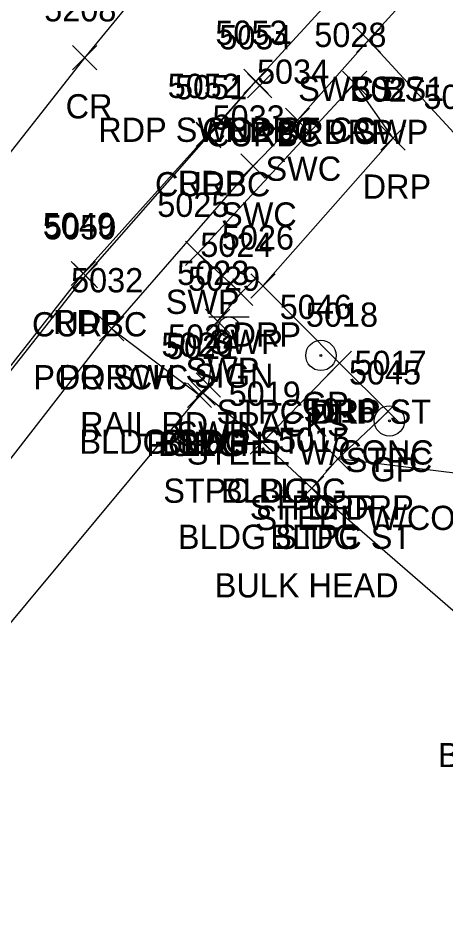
# Model space of a CAD drawing. Extents: x 1618146 to 1620418, y 640749 to 641927.
# Drawn here: x 1620267.4 to 1620302.7, y 640856.8 to 640931.1 of the extents above; entities that cross this region are included whole.
import ezdxf

# ---------------------------------------------------------------- set-up
doc = ezdxf.new("R2010")
doc.units = 0
for name, color, linetype in [('L_A', 7, 'Continuous'), ('L_C', 7, 'Continuous'), ('L_I', 7, 'Continuous'), ('L_TIC', 7, 'Continuous'), ('LBC', 7, 'Continuous'), ('LBF', 7, 'Continuous'), ('LELB', 7, 'Continuous'), ('P_A', 7, 'Continuous'), ('P_I', 7, 'Continuous'), ('P_TIC', 7, 'Continuous'), ('PET', 7, 'Continuous'), ('PRC', 7, 'Continuous'), ('R_A', 7, 'Continuous'), ('R_C', 7, 'Continuous'), ('R_I', 7, 'Continuous'), ('R_TIC', 7, 'Continuous'), ('RC', 7, 'Continuous'), ('RDP', 7, 'Continuous'), ('RGP', 7, 'Continuous'), ('RSW', 7, 'Continuous'), ('S_A', 7, 'Continuous'), ('S_C', 7, 'Continuous'), ('S_I', 7, 'Continuous'), ('SSGN', 7, 'Continuous')]:
    doc.layers.add(name, color=color, linetype=linetype)

msp = doc.modelspace()

# ---------------------------------------------------------------- linework, layer by layer
at = {"layer": 'L_TIC'}
for points in [[(1620295.264, 640928.294), (1620297.264, 640930.294)], [(1620297.264, 640928.294), (1620295.264, 640930.294)], [(1620274.079, 640904.51), (1620276.079, 640906.51)], [(1620276.079, 640904.51), (1620274.079, 640906.51)], [(1620292.873, 640901.672), (1620294.873, 640903.672)], [(1620294.873, 640901.672), (1620292.873, 640903.672)], [(1620281.333, 640899.011), (1620283.333, 640901.011)], [(1620283.333, 640899.011), (1620281.333, 640901.011)], [(1620281.333, 640899.011), (1620283.333, 640901.011)], [(1620283.333, 640899.011), (1620281.333, 640901.011)], [(1620281.611, 640899.197), (1620283.611, 640901.197)], [(1620283.611, 640899.197), (1620281.611, 640901.197)], [(1620296.876, 640897.692), (1620298.876, 640899.692)], [(1620298.876, 640897.692), (1620296.876, 640899.692)], [(1620286.512, 640895.159), (1620288.512, 640897.159)], [(1620288.512, 640895.159), (1620286.512, 640897.159)], [(1620286.512, 640895.159), (1620288.512, 640897.159)], [(1620288.512, 640895.159), (1620286.512, 640897.159)], [(1620292.744, 640893.779), (1620294.744, 640895.779)], [(1620294.744, 640893.779), (1620292.744, 640895.779)], [(1620290.579, 640891.357), (1620292.579, 640893.357)], [(1620292.579, 640891.357), (1620290.579, 640893.357)], [(1620290.579, 640891.357), (1620292.579, 640893.357)], [(1620292.579, 640891.357), (1620290.579, 640893.357)]]:
    msp.add_lwpolyline(points, dxfattribs=at)
at = {"layer": 'LBC'}
msp.add_lwpolyline([(1620332.284, 640856.845), (1620331.644, 640857.534), (1620331.352, 640857.923), (1620308.647, 640877.482), (1620307.781, 640878.325), (1620291.579, 640892.357), (1620287.512, 640896.159), (1620282.611, 640900.197), (1620282.333, 640900.011), (1620250.859, 640862.217)], dxfattribs=at)
at = {"layer": 'LBF'}
for points in [[(1620282.333, 640900.011), (1620275.079, 640905.51)], [(1620291.579, 640892.357), (1620293.744, 640894.779), (1620297.876, 640898.692), (1620293.873, 640902.672), (1620287.512, 640896.159)]]:
    msp.add_lwpolyline(points, dxfattribs=at)
at = {"layer": 'LELB'}
msp.add_lwpolyline([(1620336.269, 640857.028), (1620321.811, 640891.079), (1620314, 640906.57), (1620304.27, 640920.632), (1620296.264, 640929.294)], dxfattribs=at)
at = {"layer": 'P_TIC'}
for points in [[(1620271.862, 640926.85), (1620273.862, 640928.85)], [(1620273.862, 640926.85), (1620271.862, 640928.85)], [(1620285.98, 640924.917), (1620287.98, 640926.917)], [(1620287.98, 640924.917), (1620285.98, 640926.917)], [(1620282.046, 640920.534), (1620284.046, 640922.534)], [(1620284.046, 640920.534), (1620282.046, 640922.534)], [(1620271.752, 640909.066), (1620273.752, 640911.066)], [(1620273.752, 640909.066), (1620271.752, 640911.066)]]:
    msp.add_lwpolyline(points, dxfattribs=at)
at = {"layer": 'PET'}
msp.add_lwpolyline([(1620242.431, 640871.412), (1620272.752, 640910.066), (1620283.046, 640921.534), (1620286.98, 640925.917)], dxfattribs=at)
at = {"layer": 'PRC'}
msp.add_lwpolyline([(1620386.404, 641071.706), (1620361.021, 641035.235), (1620336.241, 641002.906), (1620316.225, 640977.168), (1620300.323, 640960.311), (1620296.609, 640956.784), (1620272.862, 640927.85), (1620252.181, 640901.579), (1620233.904, 640877.595)], dxfattribs=at)
at = {"layer": 'R_TIC'}
for points in [[(1620295.264, 640928.294), (1620297.264, 640930.294)], [(1620297.264, 640928.294), (1620295.264, 640930.294)], [(1620285.98, 640924.917), (1620287.98, 640926.917)], [(1620287.98, 640924.917), (1620285.98, 640926.917)], [(1620285.98, 640924.917), (1620287.98, 640926.917)], [(1620287.98, 640924.917), (1620285.98, 640926.917)], [(1620286.299, 640924.544), (1620288.299, 640926.544)], [(1620288.299, 640924.544), (1620286.299, 640926.544)], [(1620294.133, 640924.738), (1620296.133, 640926.738)], [(1620296.133, 640924.738), (1620294.133, 640926.738)], [(1620294.133, 640924.738), (1620296.133, 640926.738)], [(1620296.133, 640924.738), (1620294.133, 640926.738)], [(1620289.412, 640921.708), (1620291.412, 640923.708)], [(1620291.412, 640921.708), (1620289.412, 640923.708)], [(1620282.078, 640920.427), (1620284.078, 640922.427)], [(1620284.078, 640920.427), (1620282.078, 640922.427)], [(1620297.295, 640920.228), (1620299.295, 640922.228)], [(1620299.295, 640920.228), (1620297.295, 640922.228)], [(1620285.747, 640917.928), (1620287.747, 640919.928)], [(1620287.747, 640917.928), (1620285.747, 640919.928)], [(1620281.187, 640910.732), (1620283.187, 640912.732)], [(1620283.187, 640910.732), (1620281.187, 640912.732)], [(1620271.934, 640908.877), (1620273.934, 640910.877)], [(1620273.934, 640908.877), (1620271.934, 640910.877)], [(1620286.564, 640908.036), (1620288.564, 640910.036)], [(1620288.564, 640908.036), (1620286.564, 640910.036)], [(1620284.734, 640907.432), (1620286.734, 640909.432)], [(1620286.734, 640907.432), (1620284.734, 640909.432)], [(1620282.82, 640905.117), (1620284.82, 640907.117)], [(1620284.82, 640905.117), (1620282.82, 640907.117)], [(1620274.079, 640904.51), (1620276.079, 640906.51)], [(1620276.079, 640904.51), (1620274.079, 640906.51)], [(1620292.873, 640901.672), (1620294.873, 640903.672)], [(1620294.873, 640901.672), (1620292.873, 640903.672)], [(1620282.065, 640899.867), (1620284.065, 640901.867)], [(1620284.065, 640899.867), (1620282.065, 640901.867)], [(1620281.611, 640899.197), (1620283.611, 640901.197)], [(1620283.611, 640899.197), (1620281.611, 640901.197)], [(1620292.744, 640893.779), (1620294.744, 640895.779)], [(1620294.744, 640893.779), (1620292.744, 640895.779)]]:
    msp.add_lwpolyline(points, dxfattribs=at)
at = {"layer": 'RC'}
msp.add_lwpolyline([(1620242.61, 640871.403), (1620272.934, 640909.877), (1620283.078, 640921.427), (1620286.98, 640925.917), (1620287.299, 640925.544)], dxfattribs=at)
at = {"layer": 'RDP'}
for points in [[(1620293.873, 640902.672), (1620287.564, 640909.036), (1620298.295, 640921.228), (1620295.133, 640925.738)], [(1620332.284, 640856.845), (1620331.853, 640857.601), (1620331.536, 640858.064), (1620319.856, 640889.812), (1620319.237, 640890.142), (1620321.542, 640891.388), (1620293.744, 640894.779)]]:
    msp.add_lwpolyline(points, dxfattribs=at)
at = {"layer": 'RGP'}
for p, q in [((1620292.337, 640903.311), (1620292.337, 640903.311)), ((1620297.989, 640897.915), (1620297.989, 640897.915))]:
    msp.add_line(p, q, dxfattribs=at)
for centre, radius in [((1620292.337, 640903.311), 1.25), ((1620292.337, 640903.311), 0.0833), ((1620297.989, 640897.915), 1.25), ((1620297.989, 640897.915), 0.0833)]:
    msp.add_circle(centre, radius, dxfattribs=at)
at = {"layer": 'RSW'}
for points in [[(1620246.621, 640868.861), (1620275.079, 640905.51), (1620286.747, 640918.928), (1620290.412, 640922.708), (1620296.264, 640929.294), (1620303.727, 640937.553), (1620301.599, 640941.889)], [(1620286.98, 640925.917), (1620301.599, 640941.889)], [(1620282.611, 640900.197), (1620283.065, 640900.867), (1620283.82, 640906.117), (1620285.734, 640908.432), (1620282.187, 640911.732), (1620295.133, 640925.738)]]:
    msp.add_lwpolyline(points, dxfattribs=at)
at = {"layer": 'SSGN'}
for p, q in [((1620283.098, 640906.493), (1620286.432, 640906.493)), ((1620284.745, 640905.66), (1620284.745, 640905.66))]:
    msp.add_line(p, q, dxfattribs=at)
msp.add_circle((1620284.745, 640905.66), 0.833, dxfattribs=at)

# ---------------------------------------------------------------- texts
at = {"layer": 'L_A'}
for s, p in [('BS', (1620294.705, 640924.294)), ('PORCH', (1620270.701, 640900.51)), ('STPC DRP ST', (1620283.74, 640897.672)), ('PORCH', (1620277.955, 640895.011)), ('BLDG', (1620278.923, 640895.011)), ('BLDG', (1620279.201, 640895.197)), ('STPC', (1620294.388, 640893.692)), ('STPC BLDG', (1620279.347, 640891.159)), ('BLDG', (1620284.103, 640891.159)), ('STPC DRP', (1620286.477, 640889.779)), ('BLDG STPC ST', (1620280.548, 640887.357)), ('BLDG', (1620288.17, 640887.357))]:
    msp.add_text(s, height=2, dxfattribs=at).set_placement(p)
at = {"layer": 'L_C'}
for s, p in [('BULK HEAD', (1620283.588, 640883.357)), ('BURNING BUSH', (1620301.998, 640869.362))]:
    msp.add_text(s, height=2, dxfattribs=at).set_placement(p)
at = {"layer": 'L_I'}
for s, p in [('5060', (1620300.798, 640923.632)), ('5032', (1620271.741, 640908.51)), ('5018', (1620291.102, 640905.672)), ('5020', (1620279.185, 640903.197)), ('5021', (1620279.561, 640903.011)), ('5021', (1620279.561, 640903.011)), ('5017', (1620295.105, 640901.692)), ('5019', (1620284.733, 640899.159)), ('5019', (1620284.733, 640899.159)), ('5016', (1620290.918, 640897.779)), ('5015', (1620288.808, 640895.357)), ('5015', (1620288.808, 640895.357))]:
    msp.add_text(s, height=2, dxfattribs=at).set_placement(p)
at = {"layer": 'P_A'}
for s, p in [('CR', (1620271.295, 640922.85)), ('RDP', (1620284.468, 640920.917)), ('RDP', (1620280.534, 640916.534)), ('RDP', (1620270.24, 640905.066))]:
    msp.add_text(s, height=2, dxfattribs=at).set_placement(p)
at = {"layer": 'P_I'}
for s, p in [('5208', (1620269.524, 640930.85)), ('5053', (1620283.641, 640928.917)), ('5052', (1620279.708, 640924.534)), ('5049', (1620269.406, 640913.066))]:
    msp.add_text(s, height=2, dxfattribs=at).set_placement(p)
at = {"layer": 'R_A'}
for s, p in [('SWC BS1', (1620290.469, 640924.294)), ('RDP SWC2 ST CC', (1620273.98, 640920.917)), ('CURBC', (1620282.562, 640920.917)), ('CURBC', (1620282.881, 640920.544)), ('DRP SWP', (1620288.715, 640920.738)), ('DRP', (1620292.621, 640920.738)), ('SWC', (1620287.774, 640917.708)), ('CURBC', (1620278.661, 640916.427)), ('DRP', (1620295.784, 640916.228)), ('SWC', (1620284.109, 640913.928)), ('SWP', (1620279.549, 640906.732)), ('CURBC', (1620268.517, 640904.877)), ('SWP', (1620283.096, 640903.432)), ('DRP', (1620285.053, 640904.036)), ('POR SWC', (1620268.631, 640900.51)), ('SWP', (1620281.182, 640901.117)), ('GP', (1620290.77, 640898.311)), ('DRP', (1620291.362, 640897.672)), ('SWP', (1620280.427, 640895.867)), ('BLDG SWP ST', (1620272.429, 640895.197)), ('GP', (1620296.422, 640892.915)), ('DRP', (1620291.233, 640889.779))]:
    msp.add_text(s, height=2, dxfattribs=at).set_placement(p)
at = {"layer": 'R_C'}
for p in [(1620281.29, 640894.311), (1620286.942, 640888.915)]:
    msp.add_text('STEEL W/CONC', height=2, dxfattribs=at).set_placement(p)
at = {"layer": 'R_I'}
for s, p in [('5053', (1620283.641, 640928.917)), ('5053', (1620283.641, 640928.917)), ('5028', (1620291.794, 640928.738)), ('5028', (1620291.794, 640928.738)), ('5054', (1620283.96, 640928.544)), ('5034', (1620287.073, 640925.708)), ('5051', (1620280.306, 640924.427)), ('5027', (1620294.957, 640924.228)), ('5033', (1620283.408, 640921.928)), ('5025', (1620278.848, 640914.732)), ('5050', (1620269.509, 640912.877)), ('5026', (1620284.171, 640912.036)), ('5024', (1620282.395, 640911.432)), ('5023', (1620280.482, 640909.117)), ('5032', (1620271.741, 640908.51)), ('5046', (1620288.943, 640906.311)), ('5018', (1620291.102, 640905.672)), ('5022', (1620279.727, 640903.867)), ('5020', (1620279.185, 640903.197)), ('5045', (1620294.65, 640900.915)), ('5016', (1620290.918, 640897.779))]:
    msp.add_text(s, height=2, dxfattribs=at).set_placement(p)
at = {"layer": 'S_A'}
msp.add_text('SIGN', height=2, dxfattribs=at).set_placement((1620281.883, 640900.64))
at = {"layer": 'S_C'}
msp.add_text('RAIL RD TRACKS', height=2, dxfattribs=at).set_placement((1620272.49, 640896.64))
at = {"layer": 'S_I'}
msp.add_text('5029', height=2, dxfattribs=at).set_placement((1620281.379, 640908.64))

doc.saveas('drawing.dxf')
